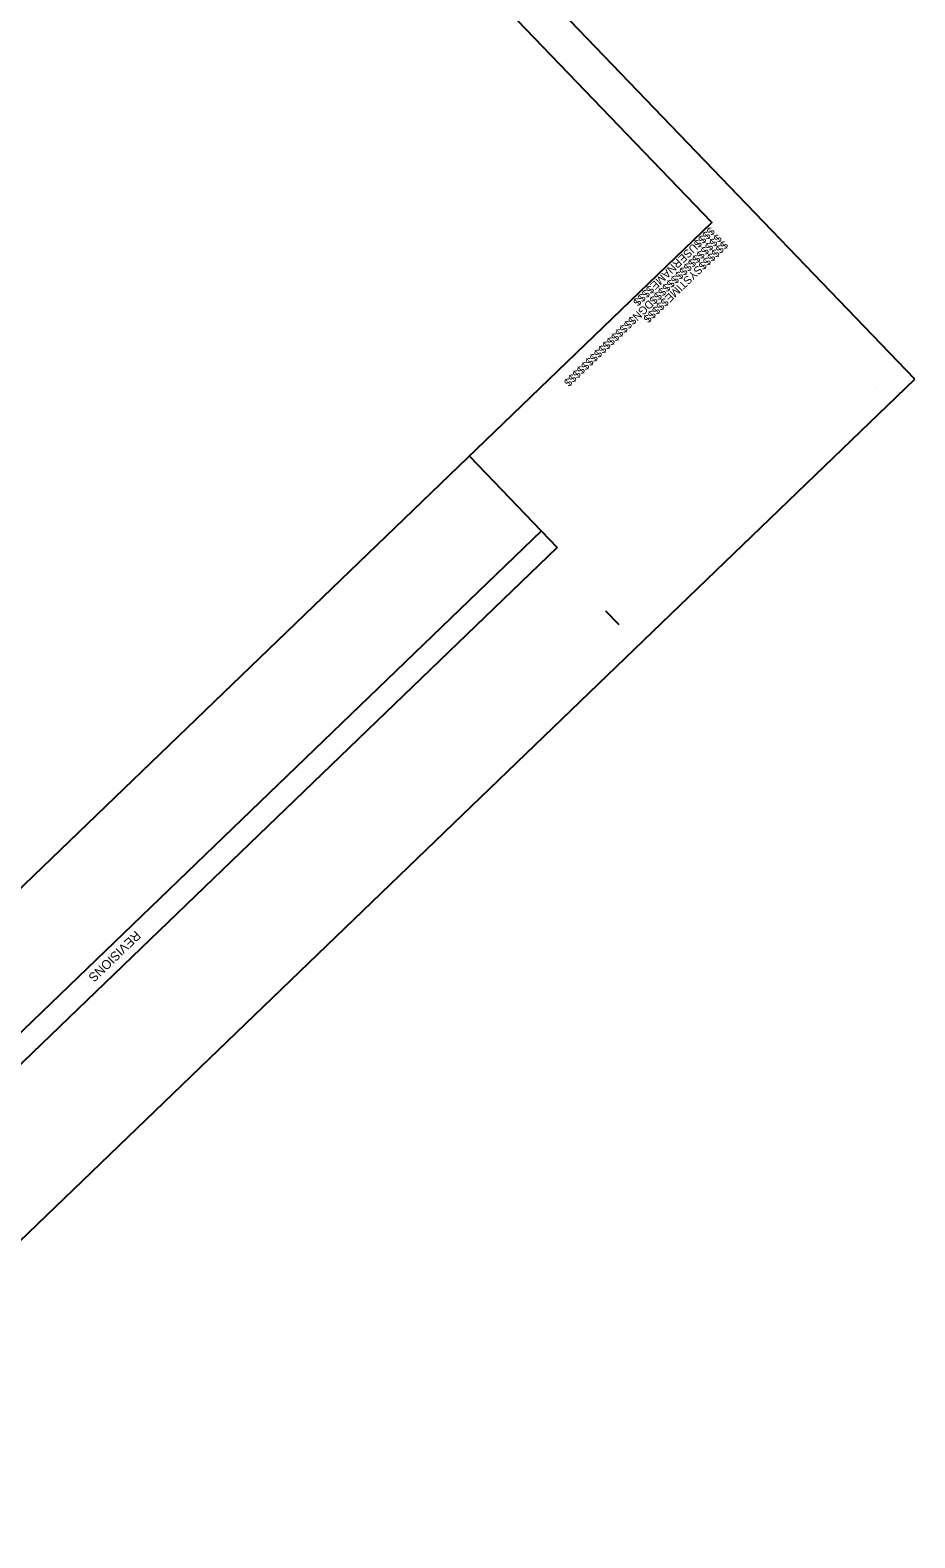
# Model space of a CAD drawing. Extents: x 474972 to 479313, y 498315 to 502691.
# Drawn here: x 478023 to 479313, y 498315 to 500513 of the extents above; entities that cross this region are included whole.
import ezdxf

# ---------------------------------------------------------------- set-up
doc = ezdxf.new("R2010")
doc.units = 0
for name, color, linetype in [('CTL Sheet Border CELL', 7, 'Continuous'), ('Sheet Block Revision CELL', 7, 'Continuous'), ('Sheet Plot Border Outside CELL', 7, 'Continuous')]:
    doc.layers.add(name, color=color, linetype=linetype)

msp = doc.modelspace()

# ---------------------------------------------------------------- linework, layer by layer
at = {"layer": 'CTL Sheet Border CELL'}
for p, q in [((479017, 500232), (479017, 500232)), ((479017, 500232), (479017, 500232)), ((479017, 500232), (479017, 500232)), ((479017, 500232), (479017, 500232)), ((479017, 500232), (479017, 500232)), ((479017, 500232), (479017, 500232)), ((479017, 500232), (479017, 500232)), ((479017, 500232), (479017, 500232)), ((479017, 500232), (479017, 500232)), ((479017, 500232), (479017, 500232)), ((479017, 500232), (479017, 500232)), ((479257.6, 499990.1), (479257.6, 499990.1)), ((479313.3, 500003.9), (479313.3, 500003.9)), ((478882, 499645.6), (478862.8, 499665.6))]:
    msp.add_line(p, q, dxfattribs=at)
msp.add_lwpolyline([(475037.9, 501013.3), (477341.4, 498619.6), (479017, 500232), (476713.6, 502625.7)], close=True, dxfattribs=at)
msp.add_lwpolyline([(478959.4, 500291.8), (478959.4, 500291.8)], dxfattribs=at)
msp.add_lwpolyline([(478959.4, 500291.8), (478959.4, 500291.8)], dxfattribs=at)
at = {"layer": 'Sheet Block Revision CELL'}
for p, q in [((478663.5, 499891.8), (478791.8, 499758.6)), ((478768.7, 499782.5), (477507.4, 498568.7)), ((478791.8, 499758.6), (477530.4, 498544.8))]:
    msp.add_line(p, q, dxfattribs=at)
at = {"layer": 'Sheet Plot Border Outside CELL'}
msp.add_lwpolyline([(479313.3, 500003.9), (476727.3, 502691.2), (474971.9, 501002.1), (477557.9, 498314.7)], close=True, dxfattribs=at)

# ---------------------------------------------------------------- texts
at = {"layer": 'CTL Sheet Border CELL'}
for s, p in [('$$$$$$$$$$$$$$$$DGN$$$$$$$$$$$$$$$$', (479024.9, 500216.2)), ('$$$$USERNAME$$$$', (479014.8, 500226.6)), ('$$$$$$SYSTIME$$$$$', (479034.2, 500206.5))]:
    msp.add_text(s, height=11.627, rotation=223.8985, dxfattribs=at).set_placement(p)
at = {"layer": 'Sheet Block Revision CELL'}
msp.add_text('REVISIONS', height=13.28, rotation=223.8985, dxfattribs=at).set_placement((478176.5, 499200.5))

doc.saveas('drawing.dxf')
